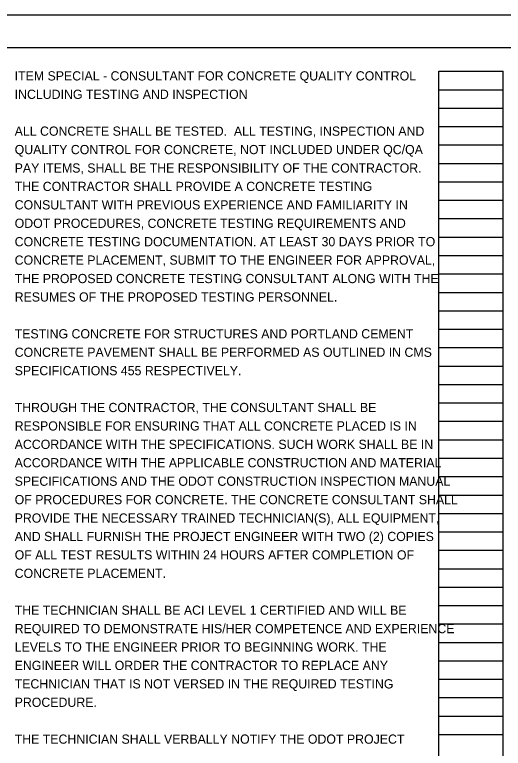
# Model space of a CAD drawing. Extents: x -14.8 to 34, y 0 to 43.2.
# Drawn here: x 17.74 to 25.16, y 10.85 to 22 of the extents above; entities that cross this region are included whole.
import ezdxf

# ---------------------------------------------------------------- set-up
doc = ezdxf.new("R2010")
doc.units = 0
for name, color, linetype in [('SH_Border', 7, 'Continuous'), ('SH_Cut_Line', 7, 'Continuous'), ('SH_Data', 7, 'Continuous'), ('SH_Text', 7, 'Continuous')]:
    doc.layers.add(name, color=color, linetype=linetype)

msp = doc.modelspace()

# ---------------------------------------------------------------- linework, layer by layer
at = {"layer": 'SH_Border'}
msp.add_lwpolyline([(2, 21.5), (33.5, 21.5), (33.5, 0.5), (2, 0.5)], close=True, dxfattribs=at)
at = {"layer": 'SH_Cut_Line'}
msp.add_lwpolyline([(0, 22), (34, 22), (34, 0), (0, 0)], close=True, dxfattribs=at)
at = {"layer": 'SH_Data'}
for p, q in [((24.18, 0.98), (24.18, 21.14)), ((24.18, 21.14), (25.16, 21.14)), ((25.16, 0.98), (25.16, 21.14)), ((24.18, 20.86), (25.16, 20.86)), ((24.18, 20.58), (25.16, 20.58)), ((24.18, 20.3), (25.16, 20.3)), ((24.18, 20.02), (25.16, 20.02)), ((24.18, 19.74), (25.16, 19.74)), ((24.18, 19.46), (25.16, 19.46)), ((24.18, 19.18), (25.16, 19.18)), ((24.18, 18.9), (25.16, 18.9)), ((24.18, 18.62), (25.16, 18.62)), ((24.18, 18.34), (25.16, 18.34)), ((24.18, 18.06), (25.16, 18.06)), ((24.18, 17.78), (25.16, 17.78)), ((24.18, 17.5), (25.16, 17.5)), ((24.18, 17.22), (25.16, 17.22)), ((24.18, 16.94), (25.16, 16.94)), ((24.18, 16.66), (25.16, 16.66)), ((24.18, 16.38), (25.16, 16.38)), ((24.18, 16.1), (25.16, 16.1)), ((24.18, 15.82), (25.16, 15.82)), ((24.18, 15.54), (25.16, 15.54)), ((24.18, 15.26), (25.16, 15.26)), ((24.18, 14.98), (25.16, 14.98)), ((24.18, 14.7), (25.16, 14.7)), ((24.18, 14.42), (25.16, 14.42)), ((24.18, 14.14), (25.16, 14.14)), ((24.18, 13.86), (25.16, 13.86)), ((24.18, 13.58), (25.16, 13.58)), ((24.18, 13.3), (25.16, 13.3)), ((24.18, 13.02), (25.16, 13.02)), ((24.18, 12.74), (25.16, 12.74)), ((24.18, 12.46), (25.16, 12.46)), ((24.18, 12.18), (25.16, 12.18)), ((24.18, 11.9), (25.16, 11.9)), ((24.18, 11.62), (25.16, 11.62)), ((24.18, 11.34), (25.16, 11.34)), ((24.18, 11.06), (25.16, 11.06))]:
    msp.add_line(p, q, dxfattribs=at)

# ---------------------------------------------------------------- texts
at = {"layer": 'SH_Text'}
for s, p in [('ITEM SPECIAL - CONSULTANT FOR CONCRETE QUALITY CONTROL ', (17.74, 21)), ('INCLUDING TESTING AND INSPECTION', (17.74, 20.72)), ('ALL CONCRETE SHALL BE TESTED.  ALL TESTING, INSPECTION AND ', (17.74, 20.16)), ('QUALITY CONTROL FOR CONCRETE, NOT INCLUDED UNDER QC/QA ', (17.74, 19.88)), ('PAY ITEMS, SHALL BE THE RESPONSIBILITY OF THE CONTRACTOR. ', (17.74, 19.6)), ('THE CONTRACTOR SHALL PROVIDE A CONCRETE TESTING ', (17.74, 19.32)), ('CONSULTANT WITH PREVIOUS EXPERIENCE AND FAMILIARITY IN ', (17.74, 19.04)), ('ODOT PROCEDURES, CONCRETE TESTING REQUIREMENTS AND ', (17.74, 18.76)), ('CONCRETE TESTING DOCUMENTATION. AT LEAST 30 DAYS PRIOR TO ', (17.74, 18.48)), ('CONCRETE PLACEMENT, SUBMIT TO THE ENGINEER FOR APPROVAL, ', (17.74, 18.2)), ('THE PROPOSED CONCRETE TESTING CONSULTANT ALONG WITH THE ', (17.74, 17.92)), ('RESUMES OF THE PROPOSED TESTING PERSONNEL.', (17.74, 17.64)), ('TESTING CONCRETE FOR STRUCTURES AND PORTLAND CEMENT ', (17.74, 17.08)), ('CONCRETE PAVEMENT SHALL BE PERFORMED AS OUTLINED IN CMS ', (17.74, 16.8)), ('SPECIFICATIONS 455 RESPECTIVELY.', (17.74, 16.52)), ('THROUGH THE CONTRACTOR, THE CONSULTANT SHALL BE ', (17.74, 15.96)), ('RESPONSIBLE FOR ENSURING THAT ALL CONCRETE PLACED IS IN ', (17.74, 15.68)), ('ACCORDANCE WITH THE SPECIFICATIONS. SUCH WORK SHALL BE IN ', (17.74, 15.4)), ('ACCORDANCE WITH THE APPLICABLE CONSTRUCTION AND MATERIAL ', (17.74, 15.12)), ('SPECIFICATIONS AND THE ODOT CONSTRUCTION INSPECTION MANUAL ', (17.74, 14.84)), ('OF PROCEDURES FOR CONCRETE. THE CONCRETE CONSULTANT SHALL ', (17.74, 14.56)), ('PROVIDE THE NECESSARY TRAINED TECHNICIAN(S), ALL EQUIPMENT, ', (17.74, 14.28)), ('AND SHALL FURNISH THE PROJECT ENGINEER WITH TWO (2) COPIES ', (17.74, 14)), ('OF ALL TEST RESULTS WITHIN 24 HOURS AFTER COMPLETION OF ', (17.74, 13.72)), ('CONCRETE PLACEMENT.', (17.74, 13.44)), ('THE TECHNICIAN SHALL BE ACI LEVEL 1 CERTIFIED AND WILL BE ', (17.74, 12.88)), ('REQUIRED TO DEMONSTRATE HIS/HER COMPETENCE AND EXPERIENCE ', (17.74, 12.6)), ('LEVELS TO THE ENGINEER PRIOR TO BEGINNING WORK. THE ', (17.74, 12.32)), ('ENGINEER WILL ORDER THE CONTRACTOR TO REPLACE ANY ', (17.74, 12.04)), ('TECHNICIAN THAT IS NOT VERSED IN THE REQUIRED TESTING ', (17.74, 11.76)), ('PROCEDURE.', (17.74, 11.48)), ('THE TECHNICIAN SHALL VERBALLY NOTIFY THE ODOT PROJECT ', (17.74, 10.92))]:
    msp.add_text(s, height=0.14, dxfattribs=at).set_placement(p)

doc.saveas('drawing.dxf')
